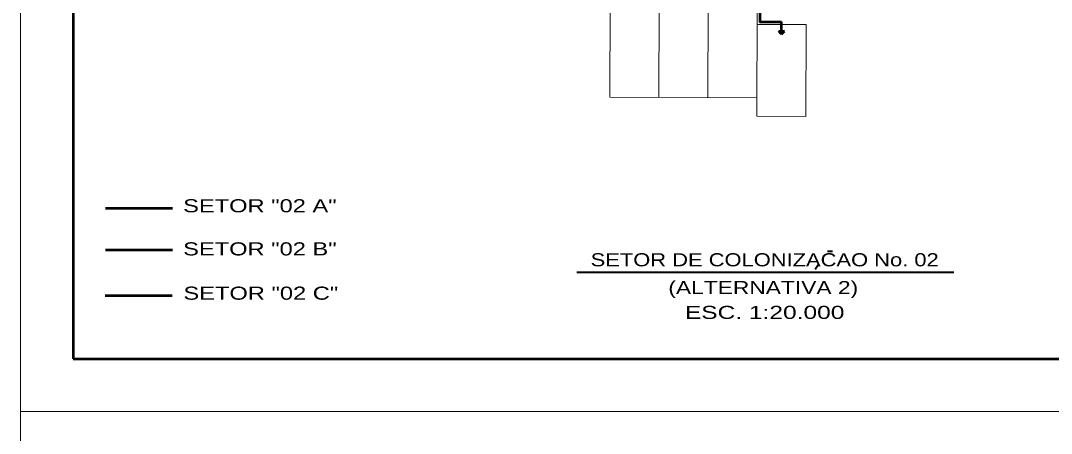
# Model space of a CAD drawing. Extents: x 312964 to 351929, y 9004151 to 9034973.
# Drawn here: x 334316 to 338250, y 9017848 to 9019423 of the extents above; entities that cross this region are included whole.
import ezdxf
from ezdxf.enums import TextEntityAlignment as Align

# ---------------------------------------------------------------- set-up
doc = ezdxf.new("R2010")
doc.units = 0
doc.header["$LTSCALE"] = 10
doc.layers.add('1', color=7, linetype='Continuous', lineweight=13)
doc.layers.add('2', color=7, linetype='Continuous', lineweight=53)

msp = doc.modelspace()

# ---------------------------------------------------------------- linework, layer by layer
at = {"layer": '1', "lineweight": 53}
for p, q in [((334516.19, 9021632.19), (334516.19, 9018132.19)), ((334639.86, 9018707.14), (334895.8, 9018707.14)), ((334639.86, 9018548.13), (334895.8, 9018548.13)), ((334638.67, 9018373.62), (334894.62, 9018373.62)), ((334516.19, 9018132.19), (340056.19, 9018132.19))]:
    msp.add_line(p, q, dxfattribs=at)
at = {"layer": '1'}
for p, q in [((336566.16, 9019480.63), (336564.83, 9019130.63)), ((336753.16, 9019479.92), (336751.83, 9019129.92)), ((336940.16, 9019479.21), (336938.83, 9019129.21)), ((337127.15, 9019478.5), (337125.56, 9019058.5)), ((337126.89, 9019408.5), (337313.89, 9019407.79)), ((337313.89, 9019407.79), (337312.56, 9019057.8)), ((336564.83, 9019130.63), (337125.83, 9019128.5)), ((337125.56, 9019058.5), (337312.56, 9019057.8)), ((340256.19, 9017932.19), (334316.19, 9017932.19))]:
    msp.add_line(p, q, dxfattribs=at)
at = {"layer": '1', "lineweight": 40}
for p, q in [((337395.88, 9018543.48), (337414.17, 9018543.48)), ((337360.98, 9018492.86), (337348.32, 9018473.15)), ((336438.92, 9018462.66), (337878.32, 9018462.66))]:
    msp.add_line(p, q, dxfattribs=at)
at = {"layer": '1'}
for points in [[(340256.19, 9022132.19), (334316.19, 9022132.19), (334316.19, 9017932.19), (340256.19, 9017932.19)], [(340256.19, 9017932.19), (334316.19, 9017932.19), (334316.19, 9013732.19), (340256.19, 9013732.19)]]:
    msp.add_lwpolyline(points, close=True, dxfattribs=at)
at = {"layer": '2'}
for p, q in [((337220.28, 9019382.3), (337220.4, 9019418.15)), ((337209.76, 9019382.33), (337231.32, 9019382.26)), ((337220.5, 9019371.52), (337209.76, 9019382.33)), ((337220.5, 9019371.52), (337231.32, 9019382.26))]:
    msp.add_line(p, q, dxfattribs=at)
msp.add_lwpolyline([(336518.41, 9019490.81), (336878.41, 9019489.44), (337137.19, 9019488.46), (337136.93, 9019418.46), (337220.43, 9019418.15)], dxfattribs=at)

# ---------------------------------------------------------------- texts
at = {"layer": '1'}
for s, width, p in [('SETOR "02 A"', 1.35, (335229.41, 9018691.63)), ('SETOR "02 B"', 1.35, (335229.41, 9018527.14)), ('SETOR DE COLONIZACAO No. 02', 1.25, (337155.94, 9018485.53)), ('(ALTERNATIVA 2)', 1.3, (337150.5, 9018379.42)), ('SETOR "02 C"', 1.35, (335233, 9018358.11)), ('ESC. 1:20.000', 1.4, (337155.76, 9018284.78))]:
    msp.add_text(s, height=50, dxfattribs=dict(at, width=width)).set_placement(p, align=Align.CENTER)

doc.saveas('drawing.dxf')
